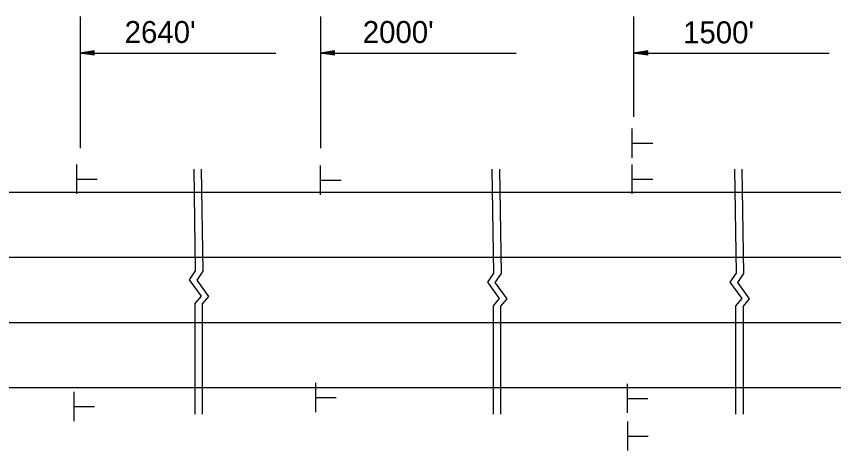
# Model space of a CAD drawing. Extents: x -100 to 745, y -1581 to -107.
# Drawn here: x 625.84 to 647.64, y -418.09 to -406.5 of the extents above; entities that cross this region are included whole.
import ezdxf

# ---------------------------------------------------------------- set-up
doc = ezdxf.new("R2010")
doc.units = 0
doc.layers.add('Default', color=7, linetype='Continuous')

msp = doc.modelspace()

# ---------------------------------------------------------------- linework, layer by layer
at = {"layer": 'Default'}
for p, q in [((627.539, -406.504), (627.539, -410.025)), ((633.955, -406.504), (633.955, -410.025)), ((642.307, -406.504), (642.307, -409.189)), ((627.914, -407.427), (627.539, -407.483)), ((627.539, -407.483), (632.758, -407.483)), ((627.914, -407.539), (627.539, -407.483)), ((627.914, -407.436), (627.601, -407.483)), ((627.914, -407.53), (627.601, -407.483)), ((627.914, -407.446), (627.666, -407.483)), ((627.914, -407.52), (627.666, -407.483)), ((627.914, -407.455), (627.728, -407.483)), ((627.914, -407.511), (627.728, -407.483)), ((627.914, -407.465), (627.792, -407.483)), ((627.914, -407.501), (627.792, -407.483)), ((627.914, -407.474), (627.854, -407.483)), ((627.914, -407.492), (627.854, -407.483)), ((627.914, -407.539), (627.914, -407.427)), ((634.33, -407.427), (633.955, -407.483)), ((633.955, -407.483), (639.174, -407.483)), ((634.33, -407.539), (633.955, -407.483)), ((634.33, -407.436), (634.017, -407.483)), ((634.33, -407.53), (634.017, -407.483)), ((634.33, -407.446), (634.082, -407.483)), ((634.33, -407.52), (634.082, -407.483)), ((634.33, -407.455), (634.144, -407.483)), ((634.33, -407.511), (634.144, -407.483)), ((634.33, -407.465), (634.208, -407.483)), ((634.33, -407.501), (634.208, -407.483)), ((634.33, -407.474), (634.271, -407.483)), ((634.33, -407.492), (634.271, -407.483)), ((634.33, -407.539), (634.33, -407.427)), ((642.682, -407.427), (642.307, -407.483)), ((642.307, -407.483), (647.526, -407.483)), ((642.682, -407.539), (642.307, -407.483)), ((642.682, -407.436), (642.37, -407.483)), ((642.682, -407.53), (642.37, -407.483)), ((642.682, -407.446), (642.434, -407.483)), ((642.682, -407.52), (642.434, -407.483)), ((642.682, -407.455), (642.497, -407.483)), ((642.682, -407.511), (642.497, -407.483)), ((642.682, -407.465), (642.56, -407.483)), ((642.682, -407.501), (642.56, -407.483)), ((642.682, -407.474), (642.623, -407.483)), ((642.682, -407.492), (642.623, -407.483)), ((642.682, -407.539), (642.682, -407.427)), ((642.271, -410.275), (642.271, -409.493)), ((642.282, -409.886), (642.816, -409.886)), ((627.448, -411.238), (627.448, -410.456)), ((633.955, -411.262), (633.955, -410.48)), ((642.269, -411.241), (642.269, -410.458)), ((627.459, -410.849), (627.993, -410.849)), ((633.966, -410.873), (634.5, -410.873)), ((642.281, -410.852), (642.815, -410.852)), ((623.741, -411.195), (629.938, -411.195)), ((629.938, -411.195), (636.023, -411.195)), ((636.023, -411.195), (644.683, -411.195)), ((644.683, -411.195), (660.675, -411.195)), ((623.786, -412.933), (629.904, -412.933)), ((629.904, -412.933), (636.023, -412.933)), ((636.023, -412.933), (644.683, -412.933)), ((644.683, -412.933), (660.675, -412.933)), ((623.786, -414.672), (629.904, -414.672)), ((629.904, -414.672), (636.023, -414.672)), ((636.023, -414.672), (644.683, -414.672)), ((644.683, -414.672), (660.675, -414.672)), ((623.832, -416.41), (629.87, -416.41)), ((629.87, -416.41), (637.305, -416.41)), ((633.828, -417.065), (633.828, -416.283)), ((636.023, -416.41), (645.6, -416.41)), ((642.143, -417.086), (642.143, -416.304)), ((644.683, -416.41), (660.675, -416.41)), ((627.38, -417.303), (627.38, -416.521)), ((633.84, -416.676), (634.374, -416.676)), ((642.154, -416.697), (642.688, -416.697)), ((627.392, -416.914), (627.926, -416.914)), ((642.152, -418.091), (642.152, -417.309)), ((642.163, -417.702), (642.697, -417.702))]:
    msp.add_line(p, q, dxfattribs=at)
for points in [[(630.571, -410.583), (630.612, -413.294), (630.45, -413.535), (630.766, -413.968), (630.6, -414.168), (630.599, -417.122)], [(630.771, -410.583), (630.812, -413.302), (630.65, -413.544), (630.966, -413.976), (630.8, -414.176), (630.799, -417.122)], [(638.527, -410.583), (638.569, -413.357), (638.406, -413.598), (638.723, -414.031), (638.556, -414.231), (638.556, -417.122)], [(638.726, -410.583), (638.769, -413.365), (638.606, -413.607), (638.923, -414.04), (638.756, -414.239), (638.756, -417.122)], [(644.997, -410.583), (645.039, -413.357), (644.877, -413.598), (645.193, -414.031), (645.027, -414.231), (645.026, -417.122)], [(645.197, -410.583), (645.239, -413.365), (645.077, -413.607), (645.393, -414.04), (645.227, -414.239), (645.226, -417.122)]]:
    msp.add_lwpolyline(points, dxfattribs=at)

# ---------------------------------------------------------------- texts
for s, p in [("2640'", (628.728, -407.215)), ("2000'", (635.08, -407.215)), ("1500'", (643.626, -407.224))]:
    msp.add_text(s, height=0.5862, dxfattribs=at).set_placement(p)

doc.saveas('drawing.dxf')
